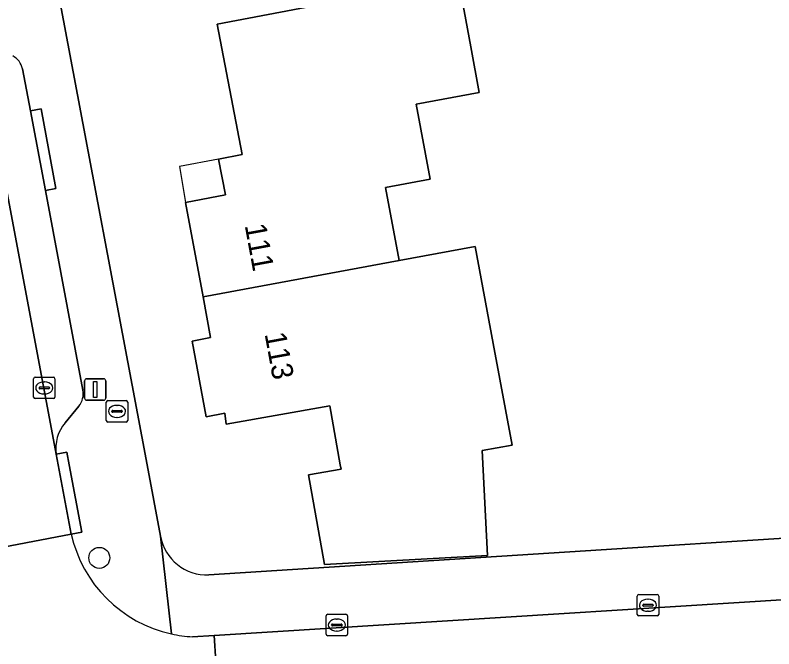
# Model space of a CAD drawing. Extents: x 159626 to 160723, y 388173 to 389416.
# Drawn here: x 160357.7 to 160393.1, y 388491.42 to 388520.98 of the extents above; entities that cross this region are included whole.
import ezdxf

# ---------------------------------------------------------------- set-up
doc = ezdxf.new("R2010")
doc.units = 0
for name, color, linetype in [('IMGEO_Boom', 7, 'Continuous'), ('IMGEO_Brandkraan', 7, 'Continuous'), ('IMGEO_Erf', 7, 'Continuous'), ('IMGEO_Kolk', 7, 'Continuous'), ('IMGEO_Lichtmast', 7, 'Continuous'), ('IMGEO_Pand', 7, 'Continuous'), ('IMGEO_Pand_nummerreeks', 7, 'Continuous'), ('IMGEO_Pand_overbouw', 7, 'Continuous'), ('IMGEO_Parkeervlak_open', 7, 'Continuous'), ('IMGEO_Rijbaan_lokaal_open', 7, 'Continuous'), ('IMGEO_Voetpad_open', 7, 'Continuous')]:
    doc.layers.add(name, color=color, linetype=linetype)

msp = doc.modelspace()

# ---------------------------------------------------------------- linework, layer by layer
at = {"layer": 'IMGEO_Boom'}
msp.add_circle((160361.626, 388495.666), 0.489, dxfattribs=at)
at = {"layer": 'IMGEO_Brandkraan'}
for p, q in [((160361.951, 388502.073), (160361.951, 388502.925)), ((160362.026, 388502.999), (160362.878, 388502.999)), ((160362.952, 388502.925), (160362.952, 388502.073)), ((160362.253, 388502.542), (160362.651, 388502.542)), ((160362.439, 388502.779), (160362.464, 388502.779)), ((160362.21, 388502.493), (160362.21, 388502.505)), ((160362.648, 388502.456), (160362.25, 388502.456)), ((160362.462, 388502.219), (160362.437, 388502.219)), ((160362.694, 388502.505), (160362.694, 388502.493)), ((160362.878, 388501.999), (160362.026, 388501.999))]:
    msp.add_line(p, q, dxfattribs=at)
for points in [[(160361.951, 388502.073), (160361.951, 388502.925)], [(160362.026, 388502.999), (160362.878, 388502.999)], [(160362.952, 388502.925), (160362.952, 388502.073)], [(160362.878, 388501.999), (160362.026, 388501.999)]]:
    msp.add_lwpolyline(points, dxfattribs=at)
for centre, radius, start, end in [((160362.028, 388502.923), 0.0765, 91.552, 178.448), ((160362.028, 388502.923), 0.0765, 91.552, 178.448), ((160362.876, 388502.923), 0.0765, 1.552, 88.448), ((160362.876, 388502.923), 0.0765, 1.552, 88.448), ((160362.25, 388502.502), 0.0403, 85.8775, 175.7526), ((160362.655, 388502.504), 0.0386, 1.7309, 96.639), ((160362.247, 388502.492), 0.0366, 178.938, 274.7102), ((160362.651, 388502.499), 0.043, 264.8664, 352.4533), ((160362.028, 388502.075), 0.0765, 181.552, 268.448), ((160362.028, 388502.075), 0.0765, 181.552, 268.448), ((160362.876, 388502.075), 0.0765, 271.552, 358.448), ((160362.876, 388502.075), 0.0765, 271.552, 358.448)]:
    msp.add_arc(centre, radius, start, end, dxfattribs=at)
for centre, major_axis, ratio, start_param, end_param in [((160362.438, 388502.499), (-0.387, 0.002), 0.722429, 4.712389, 7.853982), ((160362.463, 388502.499), (-0.39, 0.002), 0.717154, 1.570796, 4.712389)]:
    msp.add_ellipse(centre, major_axis=major_axis, ratio=ratio, start_param=start_param, end_param=end_param, dxfattribs=at)
at = {"layer": 'IMGEO_Erf'}
for points in [[(160368.426, 388523.059), (160365.177, 388522.67), (160360.276, 388523.404), (160360.13, 388524.66), (160359.823, 388524.662), (160360.292, 388522.173), (160359.702, 388522.062), (160363.856, 388500), (160364.48, 388496.683)], [(160366.742, 388494.873), (160427.265, 388498.731)]]:
    msp.add_lwpolyline(points, dxfattribs=at)
msp.add_lwpolyline([(160375.612, 388509.537), (160379.162, 388510.194), (160380.004, 388505.662), (160380.884, 388500.923), (160379.496, 388500.666), (160379.745, 388495.783), (160372.131, 388495.363), (160371.391, 388499.532), (160372.905, 388499.801), (160372.87, 388500), (160372.381, 388502.754), (160367.545, 388501.896), (160367.487, 388502.412), (160366.619, 388502.25), (160365.964, 388505.778), (160366.82, 388505.938), (160366.466, 388507.844), (160365.649, 388512.246), (160367.508, 388512.601), (160367.189, 388514.266), (160368.286, 388514.475), (160367.121, 388520.564), (160378.364, 388522.706), (160378.961, 388519.498), (160379.356, 388517.378), (160376.406, 388516.829), (160377.057, 388513.335), (160374.977, 388512.947)], close=True, dxfattribs=at)
msp.add_arc((160366.635, 388497.057), 2.187, 189.8554, 272.8126, dxfattribs=at)
at = {"layer": 'IMGEO_Kolk'}
for p, q in [((160358.557, 388503.167), (160358.557, 388504.019)), ((160358.632, 388504.093), (160359.484, 388504.093)), ((160359.558, 388504.019), (160359.558, 388503.167)), ((160358.816, 388503.587), (160358.816, 388503.599)), ((160358.859, 388503.636), (160359.257, 388503.636)), ((160359.045, 388503.873), (160359.07, 388503.873)), ((160359.3, 388503.599), (160359.3, 388503.587)), ((160359.254, 388503.55), (160358.856, 388503.55)), ((160359.068, 388503.313), (160359.043, 388503.313)), ((160359.484, 388503.093), (160358.632, 388503.093)), ((160386.725, 388493.03), (160386.725, 388493.882)), ((160386.8, 388493.956), (160387.652, 388493.956)), ((160387.213, 388493.736), (160387.238, 388493.736)), ((160387.726, 388493.882), (160387.726, 388493.03)), ((160386.984, 388493.45), (160386.984, 388493.462)), ((160387.422, 388493.413), (160387.024, 388493.413)), ((160387.027, 388493.499), (160387.425, 388493.499)), ((160387.468, 388493.462), (160387.468, 388493.45)), ((160372.283, 388493.032), (160373.135, 388493.032)), ((160387.236, 388493.176), (160387.211, 388493.176)), ((160372.208, 388492.106), (160372.208, 388492.958)), ((160372.696, 388492.812), (160372.721, 388492.812)), ((160373.209, 388492.958), (160373.209, 388492.106)), ((160387.652, 388492.956), (160386.8, 388492.956)), ((160372.467, 388492.526), (160372.467, 388492.538)), ((160372.905, 388492.489), (160372.507, 388492.489)), ((160372.51, 388492.575), (160372.908, 388492.575)), ((160372.951, 388492.538), (160372.951, 388492.526)), ((160373.135, 388492.032), (160372.283, 388492.032)), ((160372.719, 388492.252), (160372.694, 388492.252))]:
    msp.add_line(p, q, dxfattribs=at)
for points in [[(160358.557, 388503.167), (160358.557, 388504.019)], [(160358.632, 388504.093), (160359.484, 388504.093)], [(160359.558, 388504.019), (160359.558, 388503.167)], [(160359.484, 388503.093), (160358.632, 388503.093)], [(160386.725, 388493.03), (160386.725, 388493.882)], [(160386.8, 388493.956), (160387.652, 388493.956)], [(160387.726, 388493.882), (160387.726, 388493.03)], [(160372.283, 388493.032), (160373.135, 388493.032)], [(160372.208, 388492.106), (160372.208, 388492.958)], [(160373.209, 388492.958), (160373.209, 388492.106)], [(160387.652, 388492.956), (160386.8, 388492.956)], [(160373.135, 388492.032), (160372.283, 388492.032)]]:
    msp.add_lwpolyline(points, dxfattribs=at)
for centre, radius, start, end in [((160358.634, 388504.017), 0.0765, 91.552, 178.448), ((160358.634, 388504.017), 0.0765, 91.552, 178.448), ((160359.482, 388504.017), 0.0765, 1.552, 88.448), ((160359.482, 388504.017), 0.0765, 1.552, 88.448), ((160358.856, 388503.596), 0.0403, 85.8775, 175.7526), ((160359.261, 388503.598), 0.0386, 1.7309, 96.639), ((160358.853, 388503.586), 0.0366, 178.938, 274.7102), ((160359.257, 388503.593), 0.043, 264.8664, 352.4533), ((160358.634, 388503.169), 0.0765, 181.552, 268.448), ((160358.634, 388503.169), 0.0765, 181.552, 268.448), ((160359.482, 388503.169), 0.0765, 271.552, 358.448), ((160359.482, 388503.169), 0.0765, 271.552, 358.448), ((160386.802, 388493.88), 0.0765, 91.552, 178.448), ((160386.802, 388493.88), 0.0765, 91.552, 178.448), ((160387.65, 388493.88), 0.0765, 1.552, 88.448), ((160387.65, 388493.88), 0.0765, 1.552, 88.448), ((160387.024, 388493.459), 0.0403, 85.8775, 175.7526), ((160387.021, 388493.449), 0.0366, 178.938, 274.7102), ((160387.425, 388493.456), 0.043, 264.8664, 352.4533), ((160387.429, 388493.461), 0.0386, 1.7309, 96.639), ((160372.285, 388492.956), 0.0765, 91.552, 178.448), ((160372.285, 388492.956), 0.0765, 91.552, 178.448), ((160373.133, 388492.956), 0.0765, 1.552, 88.448), ((160373.133, 388492.956), 0.0765, 1.552, 88.448), ((160386.802, 388493.032), 0.0765, 181.552, 268.448), ((160386.802, 388493.032), 0.0765, 181.552, 268.448), ((160387.65, 388493.032), 0.0765, 271.552, 358.448), ((160387.65, 388493.032), 0.0765, 271.552, 358.448), ((160372.507, 388492.535), 0.0403, 85.8775, 175.7526), ((160372.504, 388492.525), 0.0366, 178.938, 274.7102), ((160372.908, 388492.532), 0.043, 264.8664, 352.4533), ((160372.912, 388492.537), 0.0386, 1.7309, 96.639), ((160372.285, 388492.108), 0.0765, 181.552, 268.448), ((160372.285, 388492.108), 0.0765, 181.552, 268.448), ((160373.133, 388492.108), 0.0765, 271.552, 358.448), ((160373.133, 388492.108), 0.0765, 271.552, 358.448)]:
    msp.add_arc(centre, radius, start, end, dxfattribs=at)
for centre, major_axis, ratio, start_param, end_param in [((160359.044, 388503.593), (-0.387, 0.002), 0.722429, 4.712389, 7.853982), ((160359.069, 388503.593), (-0.39, 0.002), 0.717154, 1.570796, 4.712389), ((160387.212, 388493.456), (-0.387, 0.002), 0.722429, 4.712389, 7.853982), ((160387.237, 388493.456), (-0.39, 0.002), 0.717154, 1.570796, 4.712389), ((160372.695, 388492.532), (-0.387, 0.002), 0.722429, 4.712389, 7.853982), ((160372.72, 388492.532), (-0.39, 0.002), 0.717154, 1.570796, 4.712389)]:
    msp.add_ellipse(centre, major_axis=major_axis, ratio=ratio, start_param=start_param, end_param=end_param, dxfattribs=at)
at = {"layer": 'IMGEO_Lichtmast'}
for p, q in [((160361.035, 388504.021), (160361.825, 388504.021)), ((160361.825, 388504.021), (160361.035, 388504.021)), ((160360.935, 388503.121), (160360.935, 388503.921)), ((160360.935, 388503.921), (160360.935, 388503.121)), ((160361.925, 388503.921), (160361.925, 388503.121)), ((160361.925, 388503.121), (160361.925, 388503.921)), ((160361.825, 388503.021), (160361.035, 388503.021)), ((160361.035, 388503.021), (160361.825, 388503.021))]:
    msp.add_line(p, q, dxfattribs=at)
msp.add_lwpolyline([(160361.355, 388503.896), (160361.505, 388503.896), (160361.505, 388503.146), (160361.355, 388503.146), (160361.355, 388503.896)], dxfattribs=at)
for centre, start, end in [((160361.035, 388503.921), 90, 180), ((160361.035, 388503.921), 90, 180), ((160361.825, 388503.921), 0, 90), ((160361.825, 388503.921), 360, 90), ((160361.035, 388503.121), 180, 270), ((160361.035, 388503.121), 180, 270), ((160361.825, 388503.121), 270, 0), ((160361.825, 388503.121), 270, 0)]:
    msp.add_arc(centre, 0.1, start, end, dxfattribs=at)
at = {"layer": 'IMGEO_Pand'}
for points in [[(160366.466, 388507.844), (160375.612, 388509.537), (160374.977, 388512.947), (160377.057, 388513.335), (160376.406, 388516.829), (160379.356, 388517.378), (160378.961, 388519.498), (160378.364, 388522.706), (160367.121, 388520.564), (160368.286, 388514.475), (160367.189, 388514.266), (160367.508, 388512.601), (160365.649, 388512.246)], [(160380.004, 388505.662), (160379.162, 388510.194), (160375.612, 388509.537), (160366.466, 388507.844), (160366.82, 388505.938), (160365.964, 388505.778), (160366.619, 388502.25), (160367.487, 388502.412), (160367.545, 388501.896), (160372.381, 388502.754), (160372.87, 388500), (160372.905, 388499.801), (160371.391, 388499.532), (160372.131, 388495.363), (160379.745, 388495.783), (160379.496, 388500.666), (160380.884, 388500.923)]]:
    msp.add_lwpolyline(points, close=True, dxfattribs=at)
at = {"layer": 'IMGEO_Pand_overbouw'}
msp.add_lwpolyline([(160365.649, 388512.246), (160367.508, 388512.601), (160367.189, 388514.266), (160365.362, 388513.927)], close=True, dxfattribs=at)
at = {"layer": 'IMGEO_Parkeervlak_open'}
for points in [[(160355.785, 388520.824), (160359.619, 388500.498)], [(160360.863, 388503.487), (160359.11, 388512.809), (160358.413, 388516.516), (160358.044, 388518.479)], [(160360.034, 388501.964), (160360.673, 388502.745)]]:
    msp.add_lwpolyline(points, dxfattribs=at)
for centre, radius, start, end in [((160357.156, 388518.271), 0.913, 13.1846, 61.9247), ((160359.936, 388503.329), 0.941, 321.6116, 9.6627), ((160361.408, 388500.783), 1.812, 139.3324, 189.0557)]:
    msp.add_arc(centre, radius, start, end, dxfattribs=at)
at = {"layer": 'IMGEO_Rijbaan_lokaal_open'}
for points in [[(160348.215, 388533.943), (160348.568, 388532.21), (160349.798, 388525.5), (160349.925, 388524.728), (160350.008, 388524.29), (160350.3, 388522.853), (160354.588, 388500), (160354.681, 388499.504), (160355.339, 388495.817), (160360.315, 388496.776), (160359.705, 388500), (160359.619, 388500.498), (160355.785, 388520.824)], [(160360.315, 388496.776), (160355.339, 388495.817), (160356.705, 388488.393), (160357.349, 388478.621), (160357.367, 388478.346)], [(160367.38, 388485.986), (160366.987, 388492.046), (160365.977, 388491.983)]]:
    msp.add_lwpolyline(points, dxfattribs=at)
msp.add_lwpolyline([(160427.705, 388495.851), (160424.131, 388495.627), (160420.362, 388495.391), (160408.897, 388494.672), (160402.116, 388494.248), (160366.987, 388492.046), (160367.38, 388485.986), (160371.152, 388486.237), (160371.556, 388486.262), (160381.99, 388486.891), (160388.781, 388487.328), (160399.309, 388488.005), (160406.093, 388488.441), (160416.087, 388489.084), (160422.859, 388489.52), (160428.063, 388489.866)], close=True, dxfattribs=at)
for centre, radius, start, end in [((160366.311, 388498.118), 6.144, 192.6124, 257.584), ((160366.31, 388498.137), 6.163, 257.6337, 266.9034)]:
    msp.add_arc(centre, radius, start, end, dxfattribs=at)
at = {"layer": 'IMGEO_Voetpad_open'}
for points in [[(160364.99, 388492.117), (160364.48, 388496.683), (160363.856, 388500), (160359.702, 388522.062)], [(160358.044, 388518.479), (160358.413, 388516.516), (160358.909, 388516.608), (160359.601, 388512.9), (160359.11, 388512.809), (160360.863, 388503.487)], [(160360.673, 388502.745), (160360.034, 388501.964)], [(160359.619, 388500.498), (160360.11, 388500.589), (160360.22, 388500), (160360.806, 388496.867), (160360.315, 388496.776)], [(160427.265, 388498.731), (160366.742, 388494.873)], [(160364.48, 388496.683), (160364.99, 388492.117)], [(160365.977, 388491.983), (160366.987, 388492.046), (160402.116, 388494.248), (160408.897, 388494.672), (160420.362, 388495.391), (160424.131, 388495.627)]]:
    msp.add_lwpolyline(points, dxfattribs=at)
for points in [[(160358.413, 388516.516), (160359.11, 388512.809), (160359.601, 388512.9), (160358.909, 388516.608)], [(160360.315, 388496.776), (160360.806, 388496.867), (160360.22, 388500), (160360.11, 388500.589), (160359.619, 388500.498), (160359.705, 388500)]]:
    msp.add_lwpolyline(points, close=True, dxfattribs=at)
for centre, radius, start, end in [((160357.156, 388518.271), 0.913, 13.1846, 61.9247), ((160359.936, 388503.329), 0.941, 321.6116, 9.6627), ((160361.408, 388500.783), 1.812, 139.3324, 189.0557), ((160366.311, 388498.118), 6.144, 192.6124, 257.584), ((160366.635, 388497.057), 2.187, 189.8554, 272.8126), ((160366.31, 388498.137), 6.163, 257.6337, 266.9034)]:
    msp.add_arc(centre, radius, start, end, dxfattribs=at)

# ---------------------------------------------------------------- texts
at = {"layer": 'IMGEO_Pand_nummerreeks'}
for s, rotation, p in [('111', 280.3808, (160368.407, 388511.177)), ('113', 280.3818, (160369.335, 388506.112))]:
    msp.add_text(s, height=1, rotation=rotation, dxfattribs=at).set_placement(p)

doc.saveas('drawing.dxf')
